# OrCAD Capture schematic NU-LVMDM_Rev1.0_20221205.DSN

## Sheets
1 LVMDM-Connect: size A4; title: Nu-LVMDM-Connect-20220823; rev: V1.0
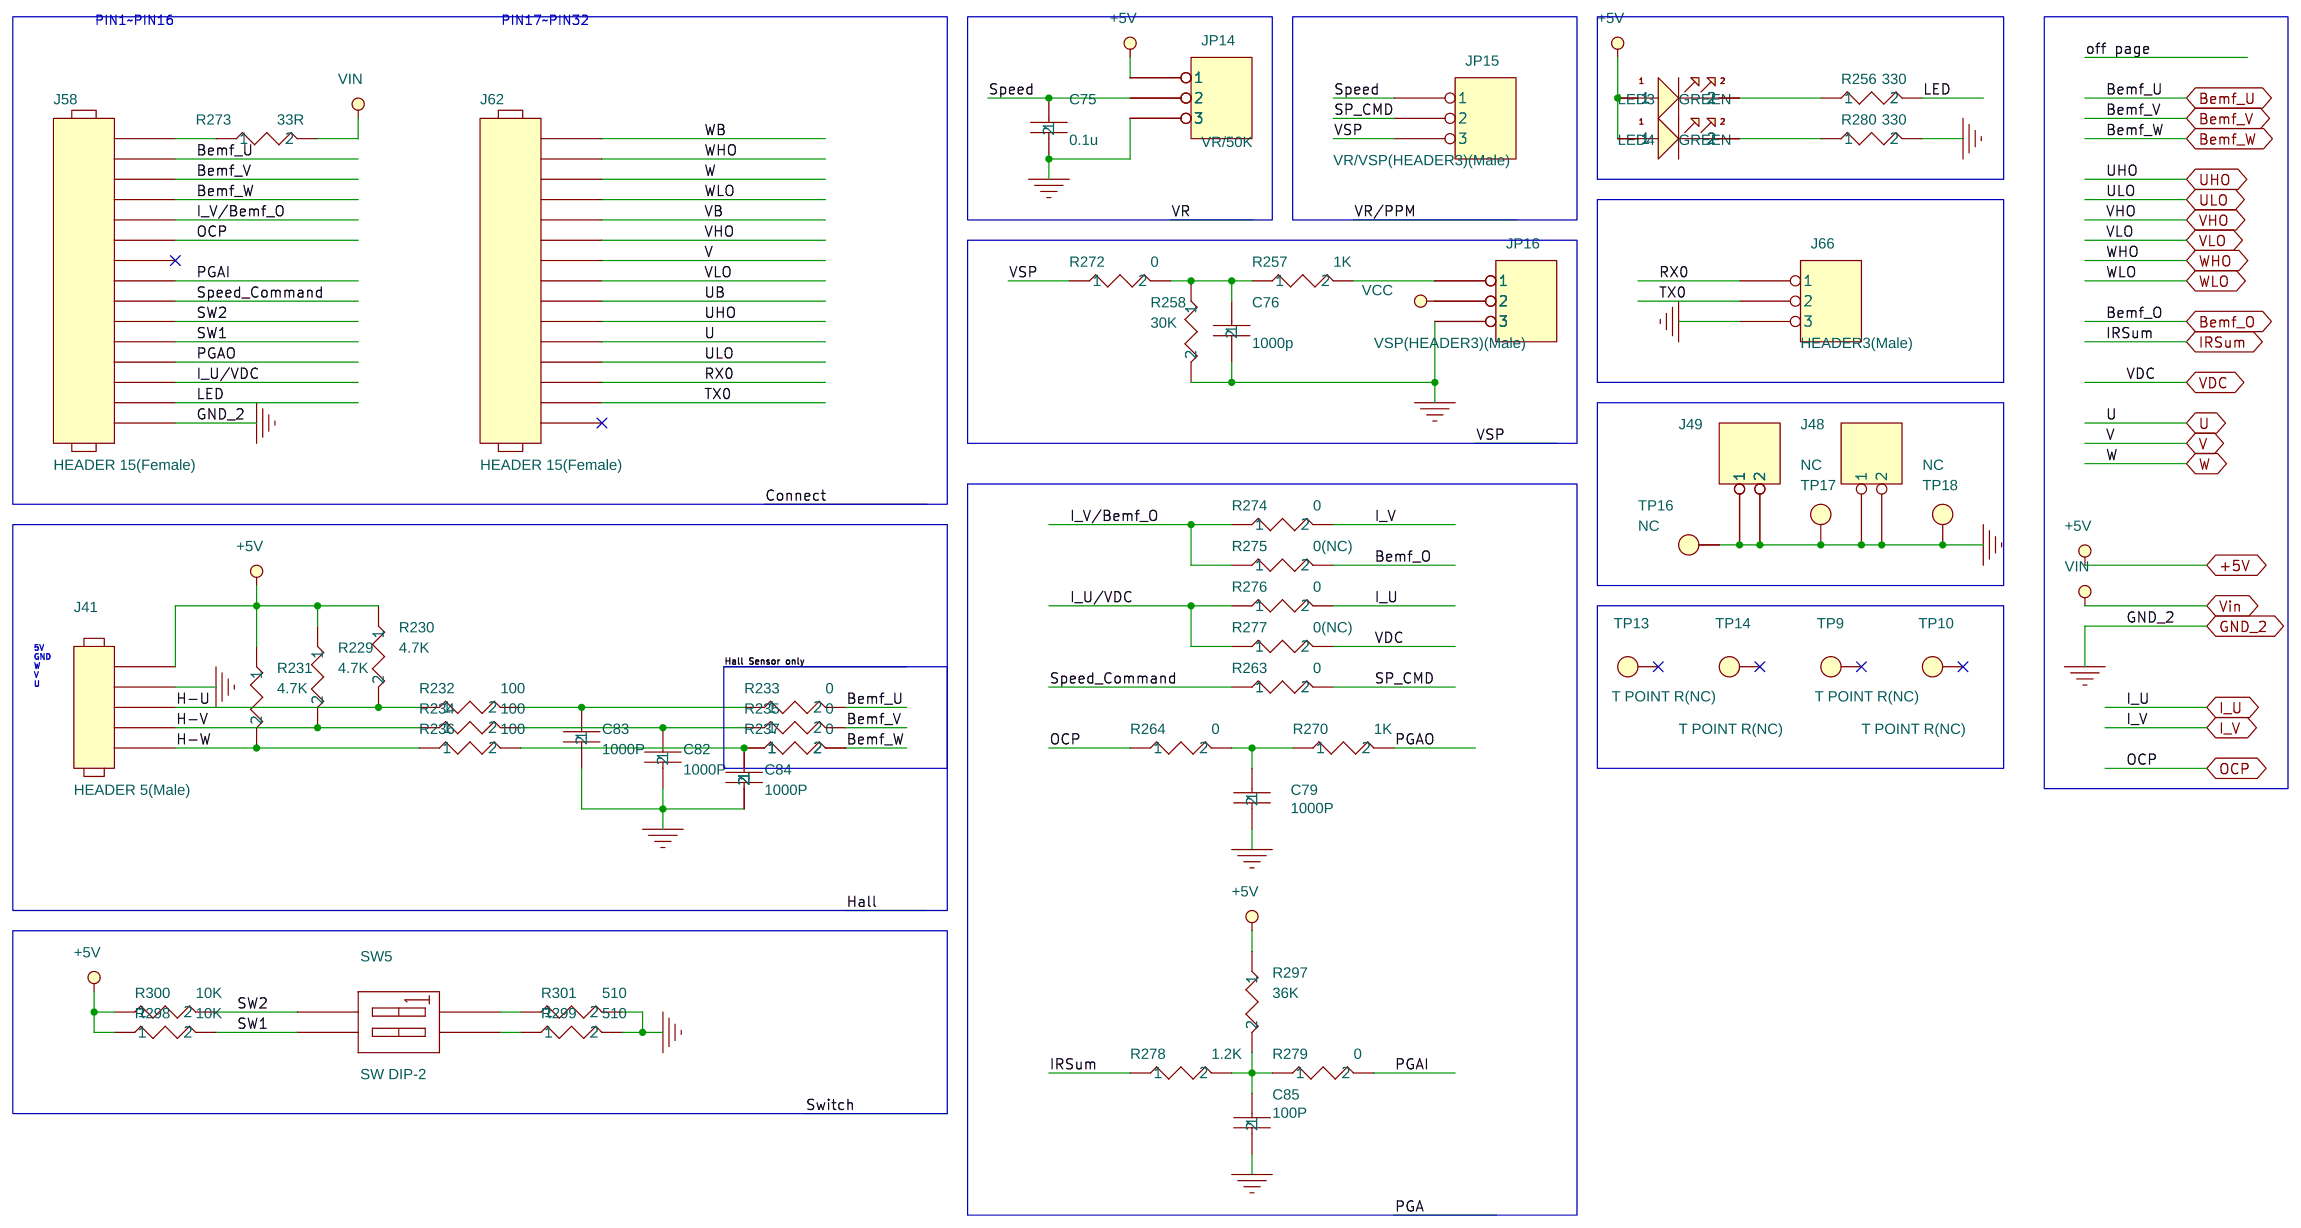
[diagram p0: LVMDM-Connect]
2 LVMDM-Power: size A4; title: Nu-LVMDM-Power-20220823
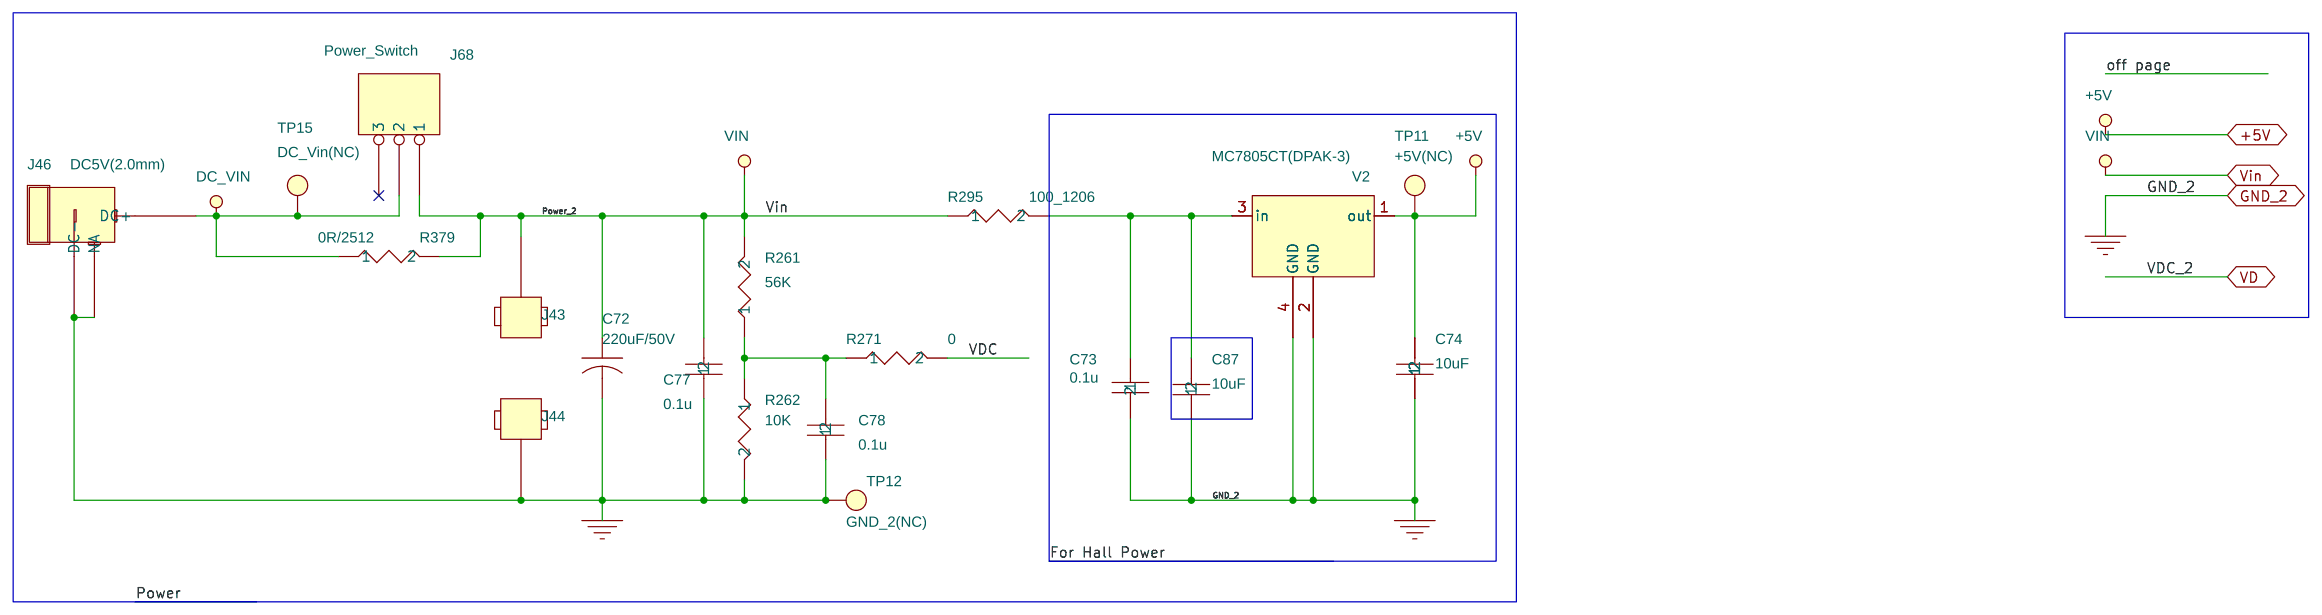
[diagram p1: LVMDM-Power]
3 LVMDM-MOS: size A4; title: Nu-LVMDM-MOS & OP-20220823
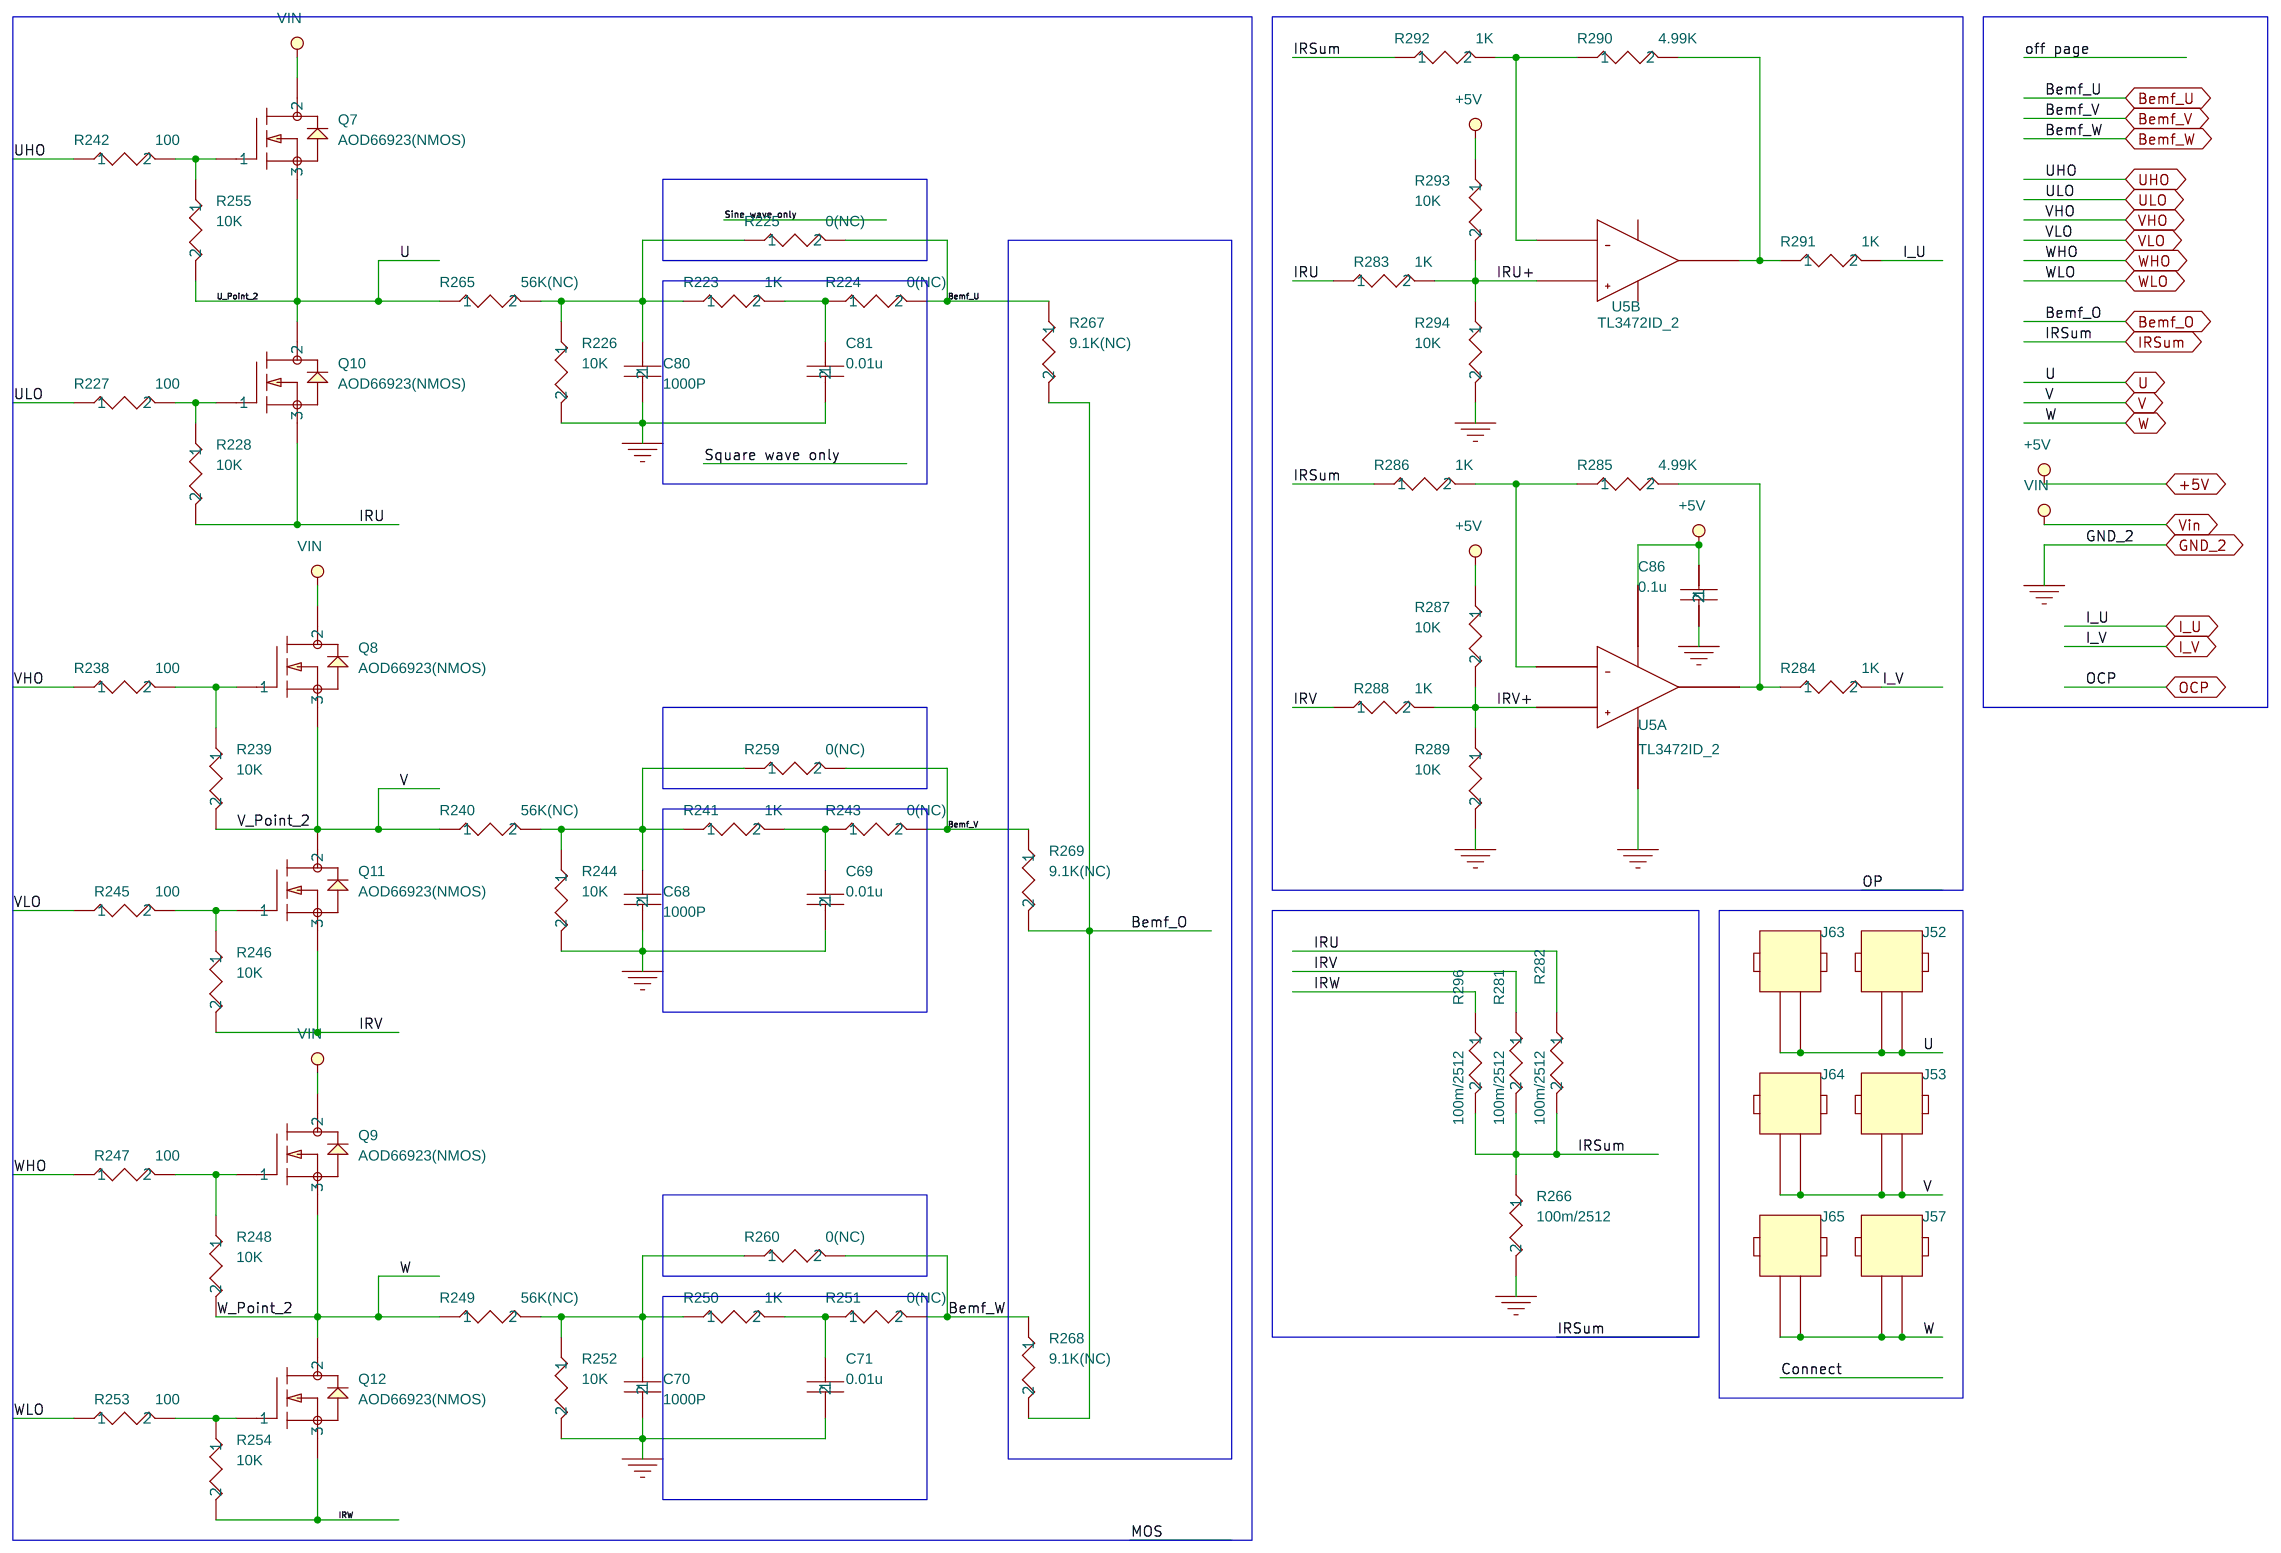
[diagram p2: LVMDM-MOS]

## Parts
sheet LVMDM-Connect
C75  0.1u  [C0603]
C76  1000p  [C0603]
C79  1000P  [C0603]
C82  1000P  [C0603]
C83  1000P  [C0603]
C84  1000P  [C0603]
C85  100P  [C0603]
J41  HEADER 5(Male)  [HEADER1X5]
J48  HEADER2(Male)  [SIP-2P]
J49  HEADER2(Male)  [SIP-2P]
J58  HEADER 15(Female)  [HEADER15X1]
J62  HEADER 15(Female)  [HEADER15X1]
J66  HEADER3(Male)  [header3]
JP14  VR/50K  [VR-10X10.3]
JP15  VR/VSP(HEADER3)(Male)  [HEADER3]
JP16  VSP(HEADER3)(Male)  [HEADER3]
LED3  GREEN  [LED0805]
LED4  GREEN  [LED0805]
R229  4.7K  [R0603]
R230  4.7K  [R0603]
R231  4.7K  [R0603]
R232  100  [R0603]
R233  0  [R0603]
R234  100  [R0603]
R235  0  [R0603]
R236  100  [R0603]
R237  0  [R0603]
R256  330  [R0603]
R257  1K  [R0603]
R258  30K  [R0603]
R263  0  [R0603]
R264  0  [R0603]
R270  1K  [R0603]
R272  0  [R0603]
R273  33R  [R0805]
R274  0  [R0603]
R275  0(NC)  [R0603]
R276  0  [R0603]
R277  0(NC)  [R0603]
R278  1.2K  [R0603]
R279  0  [R0603]
R280  330  [R0603]
R297  36K  [R0603]
R298  10K  [R0603]
R299  510  [R0603]
R300  10K  [R0603]
R301  510  [R0603]
SW5  SW DIP-2  [SW1X2]
TP9  T POINT R(NC)  [GND_H]
TP10  T POINT R(NC)  [GND_H]
TP13  T POINT R(NC)  [GND_H]
TP14  T POINT R(NC)  [GND_H]
TP16  NC  [SIP\1P]
TP17  NC  [SIP\1P]
TP18  NC  [SIP\1P]
sheet LVMDM-MOS
C68  1000P  [C0603]
C69  0.01u  [C0603]
C70  1000P  [C0603]
C71  0.01u  [C0603]
C80  1000P  [C0603]
C81  0.01u  [C0603]
C86  0.1u  [C0603]
J52  MOTOR-U  [CN-J]
J53  MOTOR-V  [CN-J]
J57  MOTOR-W  [CN-J]
J63  MOTOR-U  [Sip-2p]
J64  MOTOR-V  [Sip-2p]
J65  MOTOR-W  [Sip-2p]
Q7  AOD66923(NMOS)  [MOS_RU3060L]
Q8  AOD66923(NMOS)  [MOS_RU3060L]
Q9  AOD66923(NMOS)  [MOS_RU3060L]
Q10  AOD66923(NMOS)  [MOS_RU3060L]
Q11  AOD66923(NMOS)  [MOS_RU3060L]
Q12  AOD66923(NMOS)  [MOS_RU3060L]
R223  1K  [R0603]
R224  0(NC)  [R0603]
R225  0(NC)  [R0603]
R226  10K  [R0603]
R227  100  [R0603]
R228  10K  [R0603]
R238  100  [R0603]
R239  10K  [R0603]
R240  56K(NC)  [R0603]
R241  1K  [R0603]
R242  100  [R0603]
R243  0(NC)  [R0603]
R244  10K  [R0603]
R245  100  [R0603]
R246  10K  [R0603]
R247  100  [R0603]
R248  10K  [R0603]
R249  56K(NC)  [R0603]
R250  1K  [R0603]
R251  0(NC)  [R0603]
R252  10K  [R0603]
R253  100  [R0603]
R254  10K  [R0603]
R255  10K  [R0603]
R259  0(NC)  [R0603]
R260  0(NC)  [R0603]
R265  56K(NC)  [R0603]
R266  100m/2512  [2512]
R267  9.1K(NC)  [R0603]
R268  9.1K(NC)  [R0603]
R269  9.1K(NC)  [R0603]
R281  100m/2512  [2512]
R282  100m/2512  [2512]
R283  1K  [R0603]
R284  1K  [R0603]
R285  4.99K  [R0603]
R286  1K  [R0603]
R287  10K  [R0603]
R288  1K  [R0603]
R289  10K  [R0603]
R290  4.99K  [R0603]
R291  1K  [R0603]
R292  1K  [R0603]
R293  10K  [R0603]
R294  10K  [R0603]
R296  100m/2512  [2512]
U5  TL3472ID_2  [SO-8]  (sections A,B)
sheet LVMDM-Power
C72  220uF/50V  [C_13.4_5MM]
C73  0.1u  [C0603]
C74  10uF  [C0603]
C77  0.1u  [C0603]
C78  0.1u  [C0603]
C87  10uF  [C0603]
J43  NC  [HEADER1]
J44  NC  [HEADER1]
J46  DC5V(2.0mm)  [POWER-JACK-1]
J68  Power_Switch  [Power_Switch]
R261  56K  [R0603]
R262  10K  [R0603]
R271  0  [R0603]
R295  100_1206  [R1206]
R379  0R/2512  [2512]
TP11  +5V(NC)  [SIP\1P]
TP12  GND_2(NC)  [TEST_POINT_4MM]
TP15  DC_Vin(NC)  [TEST_POINT_4MM]
V2  MC7805CT(DPAK-3)  [SOT-89-L]

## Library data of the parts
C75 = C_0.1u_6
C76 C78 C86 = C_0.1u_1
C79 = C_0.1u_5
C68 C82 C87 = C_0.1u_3
C77 C83 = C_0.1u_4
C74 C80 C84 = C_0.1u_2
C70 C73 C85 = C_0.1u
J41 = HEADER_5
J48 = Header_0_ohm
J49 = Header_0_ohm_1
J58 J62 = HEADER_15
J66 J68 = HEADER_3
JP14 = HEADER_3_1
JP15 = HEADER_3_3
JP16 = HEADER_3_2
LED3 = LED_GREEN
LED4 = LED_GREEN_1
R229 R261 R268 = R_4.7K
R230 R265 = R_4.7K_1
R231 R269 = R_4.7K_2
R232 R283 = R_33_5
R225 R233 = R_0_6
R234 R241 = R_33
R235 R296 = R_0_9
R236 R286 = R_33_1
R237 R281 = R_0_4
R256 R285 = R_33_4
R223 R257 = R_33_2
R258 R262 R287 = R_10K
R251 R263 = R_0_7
R243 R264 R271 = R_0_2
R270 R290 = R_33_3
R266 R272 R295 = R_0
R260 R273 R379 = R_0_1
R259 R274 = R_0_3
R275 = R_0_10
R276 = R_0_11
R277 R282 = R_0_8
R278 = R_1K
R224 R279 = R_0_5
R245 R280 = R_33_6
R294 R297 = R_10K_5
R254 R298 = R_10K_1
R255 R299 = R_10K_4
R289 R300 = R_10K_3
R244 R301 = R_10K_2
SW5 = SW_DIP-2
TP9-TP18 = T_POINT_R
C69 = C_20p_1
C71 = C_20p
C81 = C_20p_2
J52 J53 J57 J63-J65 = HEADER_2
Q7 = RU3060L
Q8 = RU3060L_4
Q9 = RU3060L_1
Q10 = RU3060L_3
Q11 = RU3060L_2
Q12 = RU3060L_5
R226 = R_10K_9
R227 = R_33_9
R228 = R_10K_6
R238 = R_33_14
R239 = R_10K_10
R240 = R_4.7K_3
R242 = R_33_16
R246 = R_10K_12
R247 = R_33_12
R248 = R_10K_8
R249 = R_4.7K_5
R250 = R_33_7
R252 = R_10K_11
R253 = R_33_13
R267 = R_4.7K_4
R284 = R_33_8
R288 = R_33_15
R291 = R_33_10
R292 = R_33_11
R293 = R_10K_7
U5 = TL3472ID_2
C72 = C_10uF_10V
J43 J44 = HEADER_1
J46 = DC_JACK
V2 = LM7805CT_4

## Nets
+5V: C74.2 C86.1 J41.1 JP14.1 JP16.2 LED3.1 LED4.1 R229.1 R230.1 R231.1 R287.1 R293.1 R297.1 R298.1 R300.1 TP11.1(TP) U5.8 V2.1(out)
GND_2: C68.2 C69.2 C70.2 C71.2 C72.2 C73.2 C74.1 C75.2 C76.2 C77.1 C78.1 C79.2 C80.2 C81.2 C82.2 C83.2 C84.2 C85.2 C86.2 C87.1 J41.2 J44.1 J46.2(NA) J46.3(DC-) J48.1 J48.2 J49.1 J49.2 J58.15 J66.3 JP14.3 JP16.3 R226.2 R244.2 R252.2 R258.2 R262.2 R266.2 R280.2 R289.2 R294.2 R299.2 R301.2 TP12.1(TP) TP16.1(TP) TP17.1(TP) TP18.1(TP) U5.4 V2.2(GND) V2.4(GND)
Vin: C72.1 C77.2 J43.1 J68.1 Q7.2 Q8.2 Q9.2 R261.2 R273.2 R295.1 R379.2
Bemf_O: R267.2 R268.2 R269.2 R275.2
Bemf_U: J58.2 R224.2 R225.2 R233.2 R267.1
Bemf_V: J58.3 R235.2 R243.2 R259.2 R269.1
Bemf_W: J58.4 R237.2 R251.2 R260.2 R268.1
DC_Vin: J46.1(DC+) J68.2 R379.1 TP15.1(TP)
H-U: J41.3 R230.2 R232.1
H-V: J41.4 R229.2 R234.1
H-W: J41.5 R231.2 R236.1
I_U: R276.2 R291.2
I_U/VDC: J58.13 R276.1 R277.1
I_V: R274.2 R284.2
I_V/Bemf_O: J58.5 R274.1 R275.1
IRSum: R266.1 R278.1 R281.2 R282.2 R286.1 R292.1 R296.2
IRU: Q10.3 R228.2 R282.1 R283.1
IRU+: R283.2 R293.2 R294.1 U5.5
IRV: Q11.3 R246.2 R281.1 R288.1
IRV+: R287.2 R288.2 R289.1 U5.3
IRW: Q12.3 R254.2 R296.1
LED: J58.14 R256.2
OCP: J58.6 R264.1
PGAI: J58.8 R279.2
PGAO: J58.12 R270.2
RX0: J62.13 J66.1
SP_CMD: JP15.2 R263.2
Speed: C75.1 JP14.2 JP15.1
Speed_Command: J58.9 R263.1
SW1: J58.11 R298.2 SW5.2(A2)
SW2: J58.10 R300.2 SW5.1(A1)
TX0: J62.14 J66.2
U: J52.1 J52.2 J62.11 J63.1 J63.2 Q7.3 Q10.2 R255.2 R265.1
UB: J62.9
UHO: J62.10 R242.1
ULO: J62.12 R227.1
V: J53.1 J53.2 J62.7 J64.1 J64.2 Q8.3 Q11.2 R239.2 R240.1
VB: J62.5
VDC: R277.2
VDC (page 02-LVMDM-Power): R271.2
VHO: J62.6 R238.1
VLO: J62.8 R245.1
VSP: JP15.3 R272.1
W: J57.1 J57.2 J62.3 J65.1 J65.2 Q9.3 Q12.2 R248.2 R249.1
WB: J62.1
WHO: J62.2 R247.1
WLO: J62.4 R253.1
N20625285: C73.1 C87.2 R295.2 V2.3(in)
N20777937: C68.1 R240.2 R241.1 R244.1 R259.1
N20777941: C69.1 R241.2 R243.1
N20781935: C70.1 R249.2 R250.1 R252.1 R260.1
N20781939: C71.1 R250.2 R251.1
N20970356: C80.1 R223.1 R225.1 R226.1 R265.2
N20970360: C81.1 R223.2 R224.1
N20985482: Q8.1 R238.2 R239.1
N20985487: Q11.1 R245.2 R246.1
N20985492: Q9.1 R247.2 R248.1
N20985499: Q12.1 R253.2 R254.1
N20985540: Q7.1 R242.2 R255.1
N20985562: Q10.1 R227.2 R228.1
N20985637: R290.2 R291.1 U5.7
N20985639: R290.1 R292.2 U5.6
N20985656: R284.1 R285.2 U5.1
N20985659: R285.1 R286.2 U5.2
N20987089: C82.1 R234.2 R235.1
N20987090: C83.1 R232.2 R233.1
N20987104: C84.1 R236.2 R237.1
N20987166: C76.1 R257.1 R258.1 R272.2
N20987213: LED3.2 R256.1
N20987214: LED4.2 R280.1
N20987232: R299.1 SW5.3(B2)
N20987236: R301.1 SW5.4(B1)
N21079608: C78.2 R261.1 R262.1 R271.1
N21103668: JP16.1 R257.2
N21226980: J58.1 R273.1
N21230302: C79.1 R264.2 R270.1
N21248151: C85.1 R278.2 R279.1 R297.2

Not connected (* = marked no-connect by the designer): J58 7*; J62 15*; J68 3*; TP9 1(TP)*; TP10 1(TP)*; TP13 1(TP)*; TP14 1(TP)*

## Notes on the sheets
sheet 1
- PIN1~PIN16
- PIN17~PIN32
- 5V
  GND
  W
  V
  U
